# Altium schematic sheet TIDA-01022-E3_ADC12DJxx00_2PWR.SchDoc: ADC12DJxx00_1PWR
size 431 x 279 mm; Date: Not shown in title block; ApprovedBy: Not shown in title block; CheckedBy: Not shown in title block; Author: Not shown in title block; CompanyName: Not shown in title block; DrawnBy: Avinash N; Engineer: Not shown in title block; Organization: Not shown in title block; Address1: Not shown in title block; Address2: Not shown in title block; Address3: Not shown in title block; Address4: Not shown in title block; DocumentNumber: 1; Revision: Use project parameter SCH_Rev; SheetNumber: 9; SheetTotal: 26; PageSetup: Record=PageOptions¦CenterHorizontal=True¦CenterVertical=True¦PrintScale=1.00¦XCorrection=1.00¦YCorrection=1.00¦PrintKind=0¦BorderSize=5000000¦LeftOffset=0¦BottomOffset=0¦Orientation=2¦PaperLength=1000¦PaperWidth=1000¦Scale=100¦PaperSource=15¦PrintQuality=600¦MediaType=1¦DitherType=10¦PaperKind=Letter¦PrintScaleMode=1
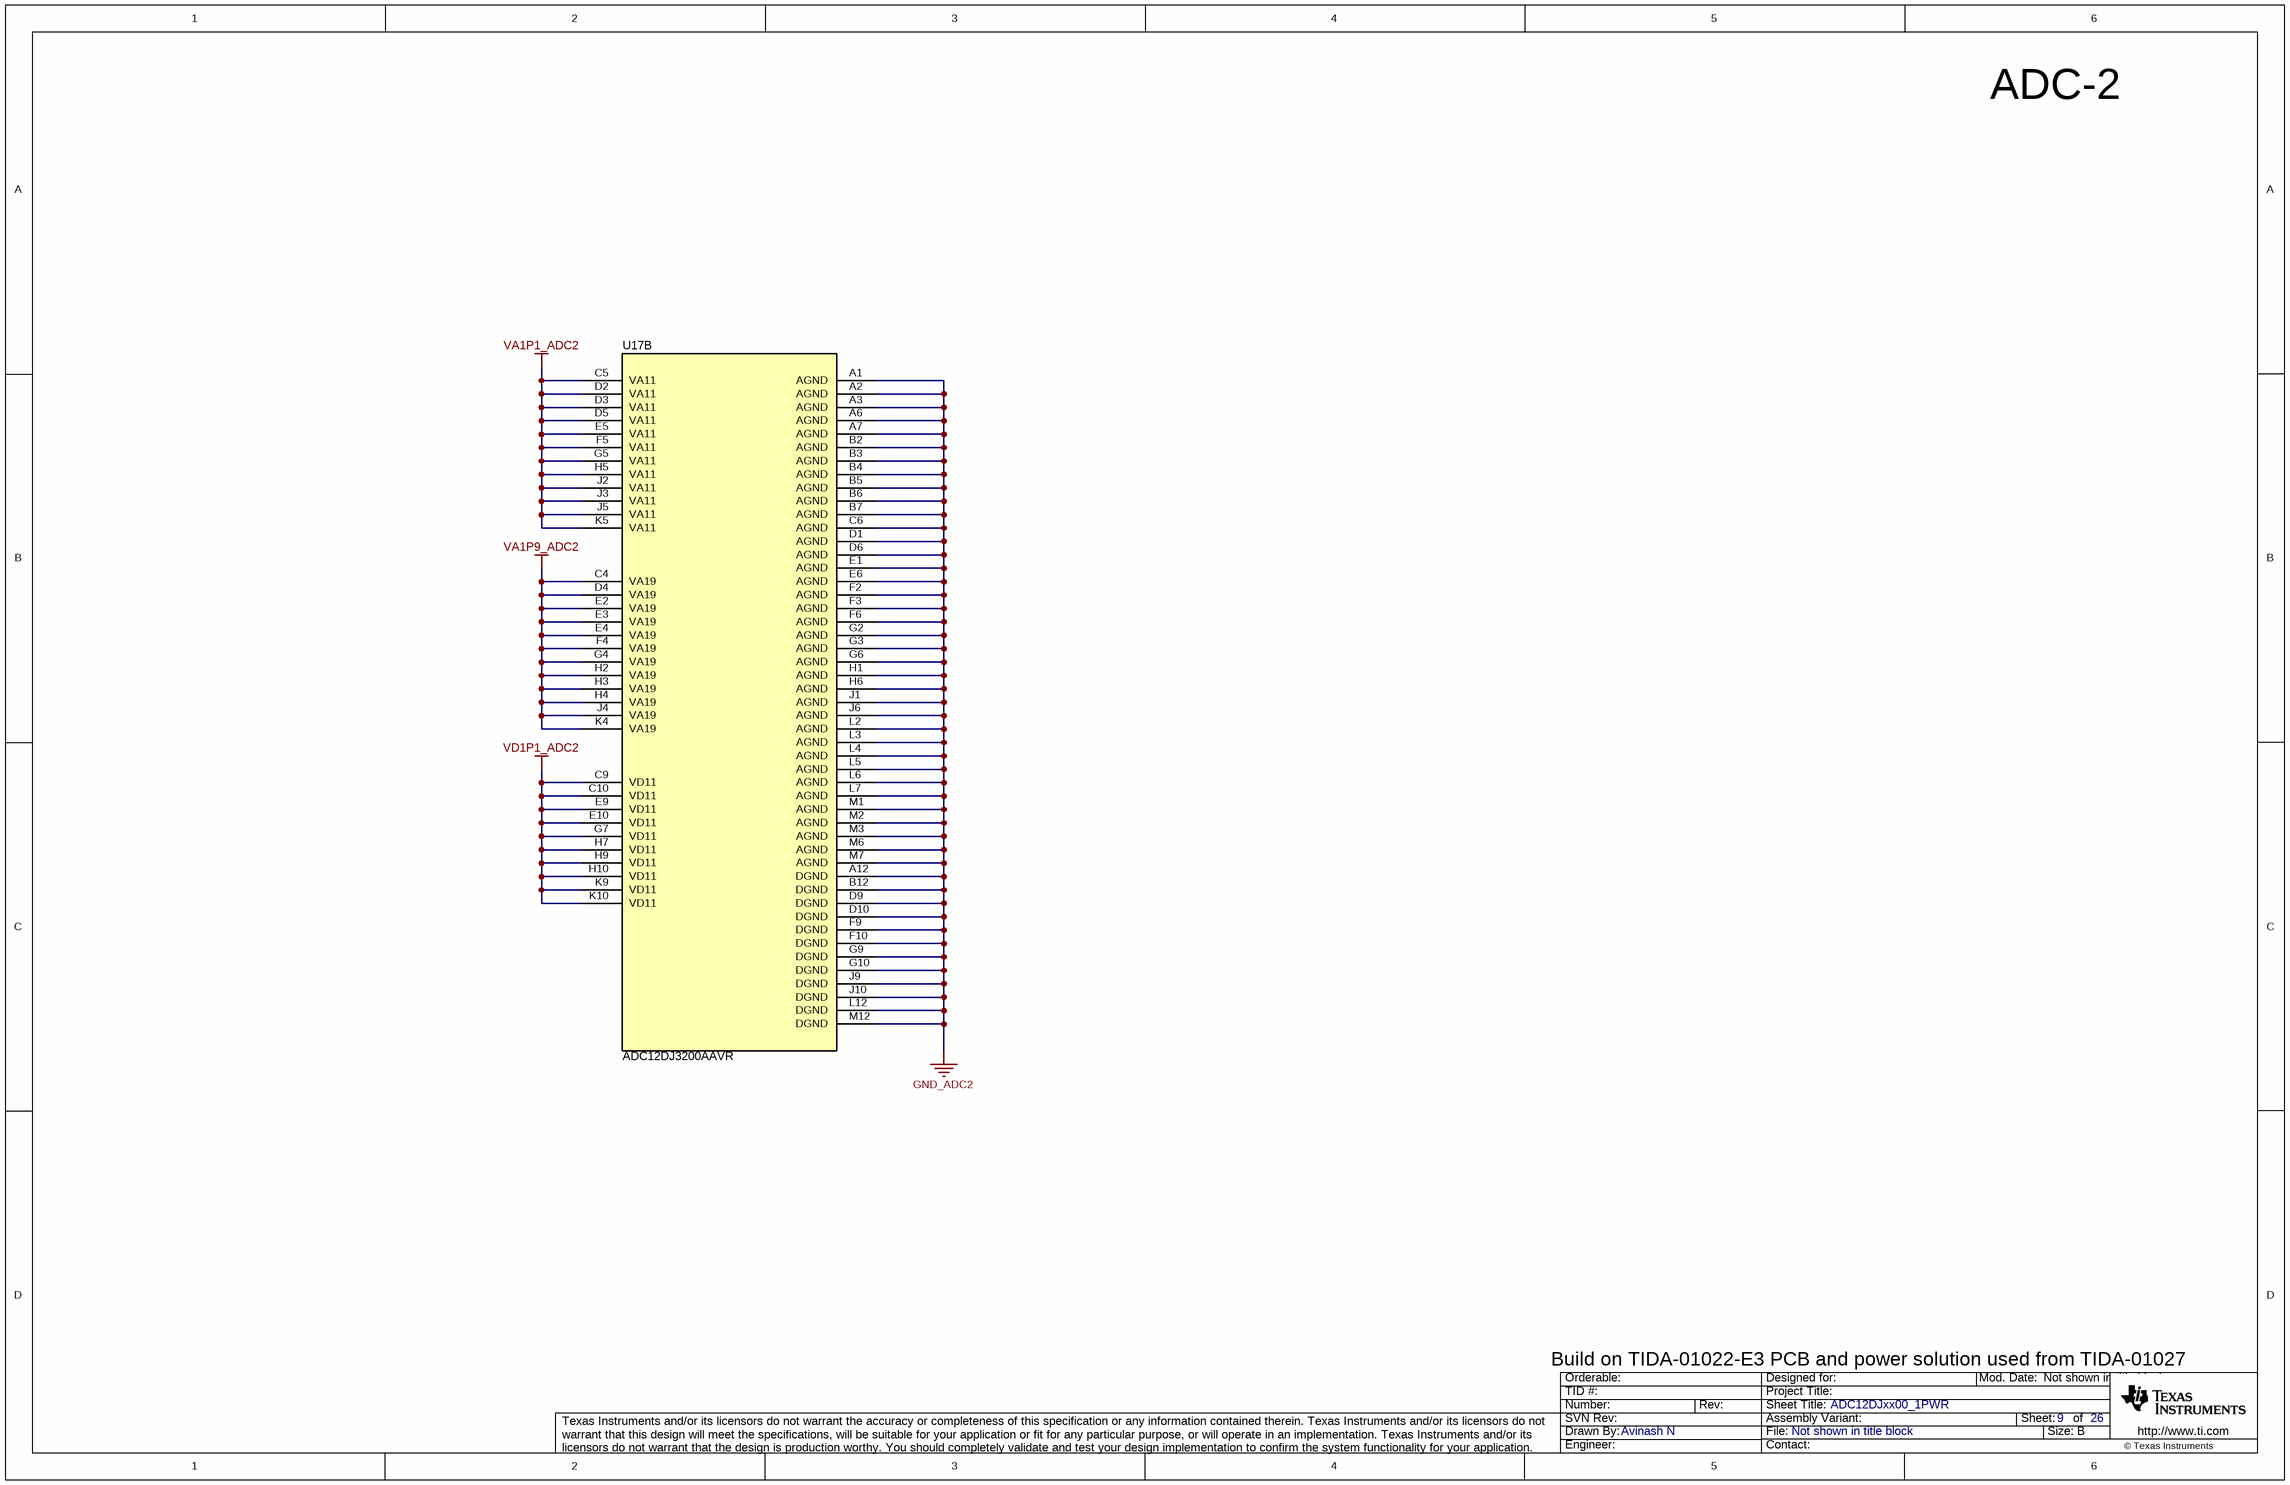
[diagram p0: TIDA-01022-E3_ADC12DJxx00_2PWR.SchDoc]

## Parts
U17  ADC12DJ3200AAVR  [AAV0144A]  (part B of 2)

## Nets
GND_ADC2: U17.A1(AGND) U17.A2(AGND) U17.A3(AGND) U17.A6(AGND) U17.A7(AGND) U17.A12(DGND) U17.B2(AGND) U17.B3(AGND) U17.B4(AGND) U17.B5(AGND) U17.B6(AGND) U17.B7(AGND) U17.B12(DGND) U17.C6(AGND) U17.D1(AGND) U17.D6(AGND) U17.D9(DGND) U17.D10(DGND) U17.E1(AGND) U17.E6(AGND) U17.F2(AGND) U17.F3(AGND) U17.F6(AGND) U17.F9(DGND) U17.F10(DGND) U17.G2(AGND) U17.G3(AGND) U17.G6(AGND) U17.G9(DGND) U17.G10(DGND) U17.H1(AGND) U17.H6(AGND) U17.J1(AGND) U17.J6(AGND) U17.J9(DGND) U17.J10(DGND) U17.L2(AGND) U17.L3(AGND) U17.L4(AGND) U17.L5(AGND) U17.L6(AGND) U17.L7(AGND) U17.L12(DGND) U17.M1(AGND) U17.M2(AGND) U17.M3(AGND) U17.M6(AGND) U17.M7(AGND) U17.M12(DGND)
VA1P1_ADC2: U17.C5(VA11) U17.D2(VA11) U17.D3(VA11) U17.D5(VA11) U17.E5(VA11) U17.F5(VA11) U17.G5(VA11) U17.H5(VA11) U17.J2(VA11) U17.J3(VA11) U17.J5(VA11) U17.K5(VA11)
VA1P9_ADC2: U17.C4(VA19) U17.D4(VA19) U17.E2(VA19) U17.E3(VA19) U17.E4(VA19) U17.F4(VA19) U17.G4(VA19) U17.H2(VA19) U17.H3(VA19) U17.H4(VA19) U17.J4(VA19) U17.K4(VA19)
VD1P1_ADC2: U17.C9(VD11) U17.C10(VD11) U17.E9(VD11) U17.E10(VD11) U17.G7(VD11) U17.H7(VD11) U17.H9(VD11) U17.H10(VD11) U17.K9(VD11) U17.K10(VD11)

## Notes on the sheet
- ADC-2
- Build on TIDA-01022-E3 PCB and power solution used from TIDA-01027

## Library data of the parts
U17 = ADC12DJ3200AAVR: 6.4-GSPS Single Channel or 3.2-GSPS Dual Channel 12-bit Analog-to-Digital Converter (ADC) Family, AAV0144A (FCBGA-144); Alternate PartNumber: ADC12DJ3200AAVT; Manufacturer: Texas Instruments; SymbolCreator: Altium; SizeArea_mm2: 100; SizeAreaWB_mm2: 144; SizeX_mm: 10; SizeZ_mm: 1.94; CompType: IC; U/M: EA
